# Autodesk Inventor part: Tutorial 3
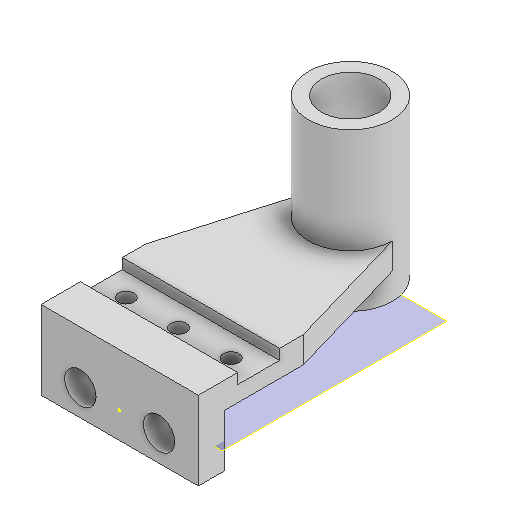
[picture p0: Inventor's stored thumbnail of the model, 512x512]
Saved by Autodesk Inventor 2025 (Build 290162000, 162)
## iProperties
Created: 2021-03
Part Number: Tutorial 3
Material: Generic
Document SubType Name: Modeling
Designer: ASUS Laptop
Density: 1 g/cm^3
Appearance: Default
Author: ASUS Laptop
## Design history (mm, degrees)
sketch "Sketch1"
  geometry: L1 (0, 0)-(30, 0); L2 (30, 0)-(30, -15); L3 (30, -15)-(26, -15); L4 (26, -15)-(26, -31); L5 (26, -31)-(30, -31); L6 (30, -31)-(30, -40); L7 (20, -40)-(20, -10); L8 (20, -10)-(0, -10); L9 (0, -10)-(0, 0); L10 (20, -40)-(30, -40)
  constraints: 20 end point, 8 perpendicular, 1 horizontal, 1 parallel, 1 point on line
  dimensions: "d0" = 16 distance of L3.end L4.end; "d1" = 15 distance of L1.end L2.end; "d2" = 40 distance between parallel lines of L1 L10; "d3" = 30 distance between parallel lines of L9 L2; "d4" = 4 distance between parallel lines of L4 L2; "d5" = 10 distance between parallel lines of L8 L1
extrude "Extrusion1" new body sketch "Sketch1" stored distance "d6" = 60; taper "d7" = 0 deg
sketch "Sketch4"
  geometry: L1 (0, 9)-(60, 9) reference; L2 (0, 9)-(14, 57); L3 (14, 57)-(46, 57); L4 (46, 57)-(60, 9); L5 (60, 9)-(0, 9); L6 (30, -31)-(30, 84.04)
  constraints: 10 end point, 1 collinear, 1 parallel, 1 vertical, 1 other
  dimensions: "d8" = 32 distance of L2.end L3.end; "d9" = 48 distance between parallel lines of L3 L1
extrude "Extrusion2" join sketch "Sketch4" distance "d10" = 10; taper "d11" = 0 deg
workplane "Work Plane1"
sketch "Sketch5"
  geometry: L1 (14, -78)-(46, -78) reference; L2 (0, 0)-(0, 10) reference; C1 r 16 at (30, -78); 1 further point
  constraints: 1 centre point, 1 midpoint
  dimensions: "d13" = 32 diameter of C1; "d14" = 30 distance from line of L2 C1.centre
extrude "Extrusion3" join sketch "Sketch5" distance "d15" = 60; taper "d16" = 0 deg
sketch "Sketch6"
  geometry: L1 (-6.213, 7.5)-(70.808, 7.5); L2 (0, -15)-(60, -15) reference; L3 (0, 0)-(0, 16) reference; C1 r 3 at (10, 7.5); C2 r 3 at (30, 7.5); C3 r 3 at (50, 7.5); 1 further point
  constraints: 3 centre point, 3 point on line, 2 end point, 2 equal radius, 1 horizontal
  dimensions: "d17" = 22.5 distance between parallel lines of L2 L1; "d18" = 10 distance from line of C1.centre L3; "d19" = 20 distance of C2.centre C1.centre; "d20" = 20 distance of C3.centre C2.centre; "d21" = 6 diameter of C1
extrude "Extrusion4" cut sketch "Sketch6" distance "d22" = 60; taper "d23" = 0 deg
sketch "Sketch8"
  geometry: L1 (15, 10)-(52.331, 10); L2 (0, 0)-(60, 0) reference; L3 (0, 0)-(0, 30) reference; C1 r 6 at (15, 10); C2 r 6 at (45, 10); 1 further point
  constraints: 2 centre point, 2 end point, 1 equal radius, 1 horizontal, 1 point on line
  dimensions: "d24" = 10 distance between parallel lines of L2 L1; "d25" = 15 distance from line of L3 L1.start; "d26" = 30 distance of C2.centre L1.start; "d27" = 12 diameter of C2
extrude "Extrusion5" cut sketch "Sketch8" stored distance "d28" = 10; taper "d29" = 0 deg
sketch "Sketch9"
  geometry: C1 r 11 at (0, 0); A1 r 16 centre (0, 0) between (-16, 0) and (16, 0) reference; 1 further point
  constraints: 1 centre point, 1 coincident
  dimensions: "d30" = 11 radius of C1
extrude "Extrusion6" cut sketch "Sketch9" extent not by distance; stored distance "d31" = 0; taper "d32" = 0 deg
body "Solid1"
sketch "Sketch7"
  geometry: 1 further point
